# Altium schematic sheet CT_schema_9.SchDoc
size 274 x 160 mm
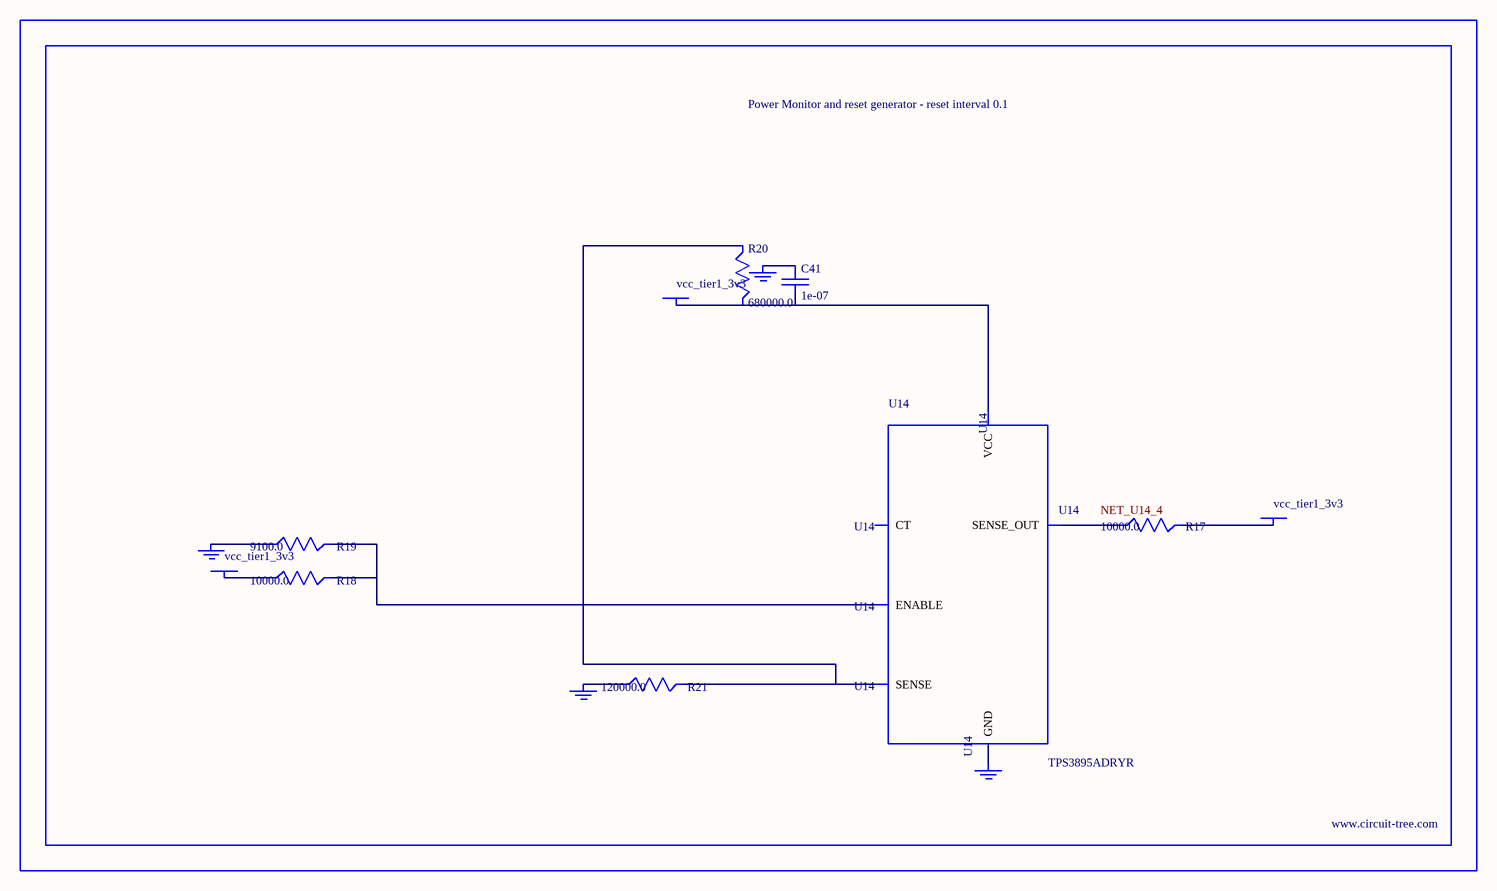
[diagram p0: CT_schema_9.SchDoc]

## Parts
BORDER8  (no value)
C41  1e-07  [C0402]
GND_INSTANCE_8_0  (no value)
GND_INSTANCE_8_1  (no value)
GND_INSTANCE_8_2  (no value)
GND_INSTANCE_8_3  (no value)
POWER_INSTANCE_8_0  vcc_tier1_3v3
POWER_INSTANCE_8_1  vcc_tier1_3v3
POWER_INSTANCE_8_2  vcc_tier1_3v3
R17  10000.0  [R0603]
R18  10000.0  [R0603]
R19  9100.0  [R0603]
R20  680000.0  [R0603]
R21  120000.0  [R0603]
U14  TPS3895ADRYR  [SON-6]

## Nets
NetC41_1: C41.1 GND_INSTANCE_8_2.0(GND)
NetC41_2: C41.2 POWER_INSTANCE_8_2.0(PWR) R20.2 U14.6(VCC)
NetGND_INSTANCE_8_0_0: GND_INSTANCE_8_0.0(GND) R19.1
NetGND_INSTANCE_8_1_0: GND_INSTANCE_8_1.0(GND) R21.1
NetGND_INSTANCE_8_3_0: GND_INSTANCE_8_3.0(GND) U14.2(GND)
NetPOWER_INSTANCE_8_0_0: POWER_INSTANCE_8_0.0(PWR) R18.1
NetPOWER_INSTANCE_8_1_0: POWER_INSTANCE_8_1.0(PWR) R17.2
NetR17_1: R17.1 U14.4(SENSE_OUT)
NetR18_2: R18.2 R19.2 U14.1(ENABLE)
NetR20_1: R20.1 R21.2 U14.3(SENSE)

Not connected (* = marked no-connect by the designer): U14 5(CT)

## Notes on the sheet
- Labels drawn without touching a wire or pin: NET_U14_4

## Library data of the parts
BORDER8 = BORDER_PAGE8
C41 = C0402C104K3RACTU
GND_INSTANCE_8_0-GND_INSTANCE_8_3 = GND
POWER_INSTANCE_8_0-POWER_INSTANCE_8_2 = PWR
R17 R18 = RC0603JR-0710KL
R19 = RC0603JR-079K1L
R20 = RC0603JR-07680KL
R21 = RC0603JR-07120KL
